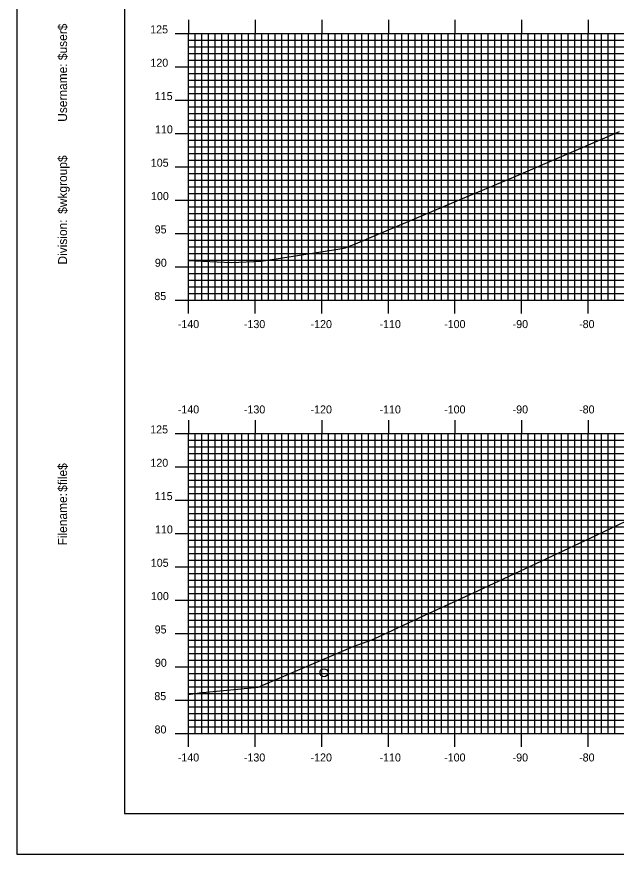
# Model space of a CAD drawing. Extents: x 1684405 to 1684749, y 461260 to 461480.
# Drawn here: x 1684405.4 to 1684495.4, y 461260 to 461385.6 of the extents above; entities that cross this region are included whole.
import ezdxf

# ---------------------------------------------------------------- set-up
doc = ezdxf.new("R2010")
doc.units = 0
for name, color, linetype in [('BORDER', 7, 'Continuous'), ('H_V ANNOTATION', 7, 'Continuous'), ('MAJOR', 7, 'Continuous'), ('MINOR', 7, 'Continuous'), ('PLOT BOUNDARY', 7, 'Continuous'), ('S_Drainage_Invert', 7, 'Continuous'), ('S_Roadway_Centerline', 7, 'Continuous')]:
    doc.layers.add(name, color=color, linetype=linetype)

msp = doc.modelspace()

# ---------------------------------------------------------------- linework, layer by layer
at = {"layer": 'BORDER'}
msp.add_lwpolyline([(1684421.6, 461266.07), (1684741.6, 461266.07), (1684741.6, 461476.07), (1684421.6, 461476.07)], close=True, dxfattribs=at)
at = {"layer": 'MAJOR'}
for p, q in [((1684431.2, 461385.08), (1684431.2, 461383.07)), ((1684441.2, 461385.08), (1684441.2, 461383.07)), ((1684451.2, 461385.08), (1684451.2, 461383.07)), ((1684461.2, 461385.08), (1684461.2, 461383.07)), ((1684471.2, 461385.08), (1684471.2, 461383.07)), ((1684481.2, 461385.08), (1684481.2, 461383.07)), ((1684491.2, 461385.08), (1684491.2, 461383.07)), ((1684429.2, 461383.07), (1684431.2, 461383.07)), ((1684431.2, 461383.07), (1684711.2, 461383.07)), ((1684431.2, 461343.07), (1684431.2, 461383.07)), ((1684431.2, 461343.07), (1684431.2, 461383.07)), ((1684431.2, 461383.07), (1684711.2, 461383.07)), ((1684441.2, 461343.07), (1684441.2, 461383.07)), ((1684451.2, 461343.07), (1684451.2, 461383.07)), ((1684461.2, 461343.07), (1684461.2, 461383.07)), ((1684471.2, 461343.07), (1684471.2, 461383.07)), ((1684481.2, 461343.07), (1684481.2, 461383.07)), ((1684491.2, 461343.07), (1684491.2, 461383.07)), ((1684429.2, 461378.07), (1684431.2, 461378.07)), ((1684431.2, 461378.07), (1684711.2, 461378.07)), ((1684429.2, 461373.07), (1684431.2, 461373.07)), ((1684431.2, 461373.07), (1684711.2, 461373.07)), ((1684429.2, 461368.07), (1684431.2, 461368.07)), ((1684431.2, 461368.07), (1684711.2, 461368.07)), ((1684429.2, 461363.07), (1684431.2, 461363.07)), ((1684431.2, 461363.07), (1684711.2, 461363.07)), ((1684429.2, 461358.07), (1684431.2, 461358.07)), ((1684431.2, 461358.07), (1684711.2, 461358.07)), ((1684429.2, 461353.07), (1684431.2, 461353.07)), ((1684431.2, 461353.07), (1684711.2, 461353.07)), ((1684429.2, 461348.07), (1684431.2, 461348.07)), ((1684431.2, 461348.07), (1684711.2, 461348.07)), ((1684429.2, 461343.07), (1684431.2, 461343.07)), ((1684431.2, 461343.07), (1684711.2, 461343.07)), ((1684431.2, 461343.07), (1684711.2, 461343.07)), ((1684431.2, 461341.07), (1684431.2, 461343.07)), ((1684441.2, 461341.07), (1684441.2, 461343.07)), ((1684451.2, 461341.07), (1684451.2, 461343.07)), ((1684461.2, 461341.07), (1684461.2, 461343.07)), ((1684471.2, 461341.07), (1684471.2, 461343.07)), ((1684481.2, 461341.07), (1684481.2, 461343.07)), ((1684491.2, 461341.07), (1684491.2, 461343.07)), ((1684431.2, 461325.08), (1684431.2, 461323.07)), ((1684441.2, 461325.08), (1684441.2, 461323.07)), ((1684451.2, 461325.08), (1684451.2, 461323.07)), ((1684461.2, 461325.08), (1684461.2, 461323.07)), ((1684471.2, 461325.08), (1684471.2, 461323.07)), ((1684481.2, 461325.08), (1684481.2, 461323.07)), ((1684491.2, 461325.08), (1684491.2, 461323.07)), ((1684429.2, 461323.07), (1684431.2, 461323.07)), ((1684431.2, 461323.07), (1684711.2, 461323.07)), ((1684431.2, 461278.07), (1684431.2, 461323.07)), ((1684431.2, 461278.07), (1684431.2, 461323.07)), ((1684431.2, 461323.07), (1684711.2, 461323.07)), ((1684441.2, 461278.07), (1684441.2, 461323.07)), ((1684451.2, 461278.07), (1684451.2, 461323.07)), ((1684461.2, 461278.07), (1684461.2, 461323.07)), ((1684471.2, 461278.07), (1684471.2, 461323.07)), ((1684481.2, 461278.07), (1684481.2, 461323.07)), ((1684491.2, 461278.07), (1684491.2, 461323.07)), ((1684429.2, 461318.07), (1684431.2, 461318.07)), ((1684431.2, 461318.07), (1684711.2, 461318.07)), ((1684429.2, 461313.07), (1684431.2, 461313.07)), ((1684431.2, 461313.07), (1684711.2, 461313.07)), ((1684429.2, 461308.07), (1684431.2, 461308.07)), ((1684431.2, 461308.07), (1684711.2, 461308.07)), ((1684429.2, 461303.07), (1684431.2, 461303.07)), ((1684431.2, 461303.07), (1684711.2, 461303.07)), ((1684429.2, 461298.07), (1684431.2, 461298.07)), ((1684431.2, 461298.07), (1684711.2, 461298.07)), ((1684429.2, 461293.07), (1684431.2, 461293.07)), ((1684431.2, 461293.07), (1684711.2, 461293.07)), ((1684429.2, 461288.07), (1684431.2, 461288.07)), ((1684431.2, 461288.07), (1684711.2, 461288.07)), ((1684429.2, 461283.07), (1684431.2, 461283.07)), ((1684431.2, 461283.07), (1684711.2, 461283.07)), ((1684429.2, 461278.07), (1684431.2, 461278.07)), ((1684431.2, 461278.07), (1684711.2, 461278.07)), ((1684431.2, 461278.07), (1684711.2, 461278.07)), ((1684431.2, 461276.07), (1684431.2, 461278.07)), ((1684441.2, 461276.07), (1684441.2, 461278.07)), ((1684451.2, 461276.07), (1684451.2, 461278.07)), ((1684461.2, 461276.07), (1684461.2, 461278.07)), ((1684471.2, 461276.07), (1684471.2, 461278.07)), ((1684481.2, 461276.07), (1684481.2, 461278.07)), ((1684491.2, 461276.07), (1684491.2, 461278.07))]:
    msp.add_line(p, q, dxfattribs=at)
at = {"layer": 'MINOR'}
for p, q in [((1684432.2, 461343.07), (1684432.2, 461383.07)), ((1684433.2, 461343.07), (1684433.2, 461383.07)), ((1684434.2, 461343.07), (1684434.2, 461383.07)), ((1684435.2, 461343.07), (1684435.2, 461383.07)), ((1684436.2, 461343.07), (1684436.2, 461383.07)), ((1684437.2, 461343.07), (1684437.2, 461383.07)), ((1684438.2, 461343.07), (1684438.2, 461383.07)), ((1684439.2, 461343.07), (1684439.2, 461383.07)), ((1684440.2, 461343.07), (1684440.2, 461383.07)), ((1684442.2, 461343.07), (1684442.2, 461383.07)), ((1684443.2, 461343.07), (1684443.2, 461383.07)), ((1684444.2, 461343.07), (1684444.2, 461383.07)), ((1684445.2, 461343.07), (1684445.2, 461383.07)), ((1684446.2, 461343.07), (1684446.2, 461383.07)), ((1684447.2, 461343.07), (1684447.2, 461383.07)), ((1684448.2, 461343.07), (1684448.2, 461383.07)), ((1684449.2, 461343.07), (1684449.2, 461383.07)), ((1684450.2, 461343.07), (1684450.2, 461383.07)), ((1684452.2, 461343.07), (1684452.2, 461383.07)), ((1684453.2, 461343.07), (1684453.2, 461383.07)), ((1684454.2, 461343.07), (1684454.2, 461383.07)), ((1684455.2, 461343.07), (1684455.2, 461383.07)), ((1684456.2, 461343.07), (1684456.2, 461383.07)), ((1684457.2, 461343.07), (1684457.2, 461383.07)), ((1684458.2, 461343.07), (1684458.2, 461383.07)), ((1684459.2, 461343.07), (1684459.2, 461383.07)), ((1684460.2, 461343.07), (1684460.2, 461383.07)), ((1684462.2, 461343.07), (1684462.2, 461383.07)), ((1684463.2, 461343.07), (1684463.2, 461383.07)), ((1684464.2, 461343.07), (1684464.2, 461383.07)), ((1684465.2, 461343.07), (1684465.2, 461383.07)), ((1684466.2, 461343.07), (1684466.2, 461383.07)), ((1684467.2, 461343.07), (1684467.2, 461383.07)), ((1684468.2, 461343.07), (1684468.2, 461383.07)), ((1684469.2, 461343.07), (1684469.2, 461383.07)), ((1684470.2, 461343.07), (1684470.2, 461383.07)), ((1684472.2, 461343.07), (1684472.2, 461383.07)), ((1684473.2, 461343.07), (1684473.2, 461383.07)), ((1684474.2, 461343.07), (1684474.2, 461383.07)), ((1684475.2, 461343.07), (1684475.2, 461383.07)), ((1684476.2, 461343.07), (1684476.2, 461383.07)), ((1684477.2, 461343.07), (1684477.2, 461383.07)), ((1684478.2, 461343.07), (1684478.2, 461383.07)), ((1684479.2, 461343.07), (1684479.2, 461383.07)), ((1684480.2, 461343.07), (1684480.2, 461383.07)), ((1684482.2, 461343.07), (1684482.2, 461383.07)), ((1684483.2, 461343.07), (1684483.2, 461383.07)), ((1684484.2, 461343.07), (1684484.2, 461383.07)), ((1684485.2, 461343.07), (1684485.2, 461383.07)), ((1684486.2, 461343.07), (1684486.2, 461383.07)), ((1684487.2, 461343.07), (1684487.2, 461383.07)), ((1684488.2, 461343.07), (1684488.2, 461383.07)), ((1684489.2, 461343.07), (1684489.2, 461383.07)), ((1684490.2, 461343.07), (1684490.2, 461383.07)), ((1684492.2, 461343.07), (1684492.2, 461383.07)), ((1684493.2, 461343.07), (1684493.2, 461383.07)), ((1684494.2, 461343.07), (1684494.2, 461383.07)), ((1684495.2, 461343.07), (1684495.2, 461383.07)), ((1684431.2, 461382.07), (1684711.2, 461382.07)), ((1684431.2, 461382.07), (1684433.21, 461382.07)), ((1684431.2, 461381.07), (1684711.2, 461381.07)), ((1684431.2, 461381.07), (1684433.21, 461381.07)), ((1684431.2, 461380.07), (1684711.2, 461380.07)), ((1684431.2, 461380.07), (1684433.21, 461380.07)), ((1684431.2, 461379.07), (1684711.2, 461379.07)), ((1684431.2, 461379.07), (1684433.21, 461379.07)), ((1684431.2, 461377.07), (1684711.2, 461377.07)), ((1684431.2, 461377.07), (1684433.21, 461377.07)), ((1684431.2, 461376.07), (1684711.2, 461376.07)), ((1684431.2, 461376.07), (1684433.21, 461376.07)), ((1684431.2, 461375.07), (1684711.2, 461375.07)), ((1684431.2, 461375.07), (1684433.21, 461375.07)), ((1684431.2, 461374.07), (1684711.2, 461374.07)), ((1684431.2, 461374.07), (1684433.21, 461374.07)), ((1684431.2, 461372.07), (1684711.2, 461372.07)), ((1684431.2, 461372.07), (1684433.21, 461372.07)), ((1684431.2, 461371.07), (1684711.2, 461371.07)), ((1684431.2, 461371.07), (1684433.21, 461371.07)), ((1684431.2, 461370.07), (1684711.2, 461370.07)), ((1684431.2, 461370.07), (1684433.21, 461370.07)), ((1684431.2, 461369.07), (1684711.2, 461369.07)), ((1684431.2, 461369.07), (1684433.21, 461369.07)), ((1684431.2, 461367.07), (1684711.2, 461367.07)), ((1684431.2, 461367.07), (1684433.21, 461367.07)), ((1684431.2, 461366.07), (1684711.2, 461366.07)), ((1684431.2, 461366.07), (1684433.21, 461366.07)), ((1684431.2, 461365.07), (1684711.2, 461365.07)), ((1684431.2, 461365.07), (1684433.21, 461365.07)), ((1684431.2, 461364.07), (1684711.2, 461364.07)), ((1684431.2, 461364.07), (1684433.21, 461364.07)), ((1684431.2, 461362.07), (1684711.2, 461362.07)), ((1684431.2, 461362.07), (1684433.21, 461362.07)), ((1684431.2, 461361.07), (1684711.2, 461361.07)), ((1684431.2, 461361.07), (1684433.21, 461361.07)), ((1684431.2, 461360.07), (1684711.2, 461360.07)), ((1684431.2, 461360.07), (1684433.21, 461360.07)), ((1684431.2, 461359.07), (1684711.2, 461359.07)), ((1684431.2, 461359.07), (1684433.21, 461359.07)), ((1684431.2, 461357.07), (1684711.2, 461357.07)), ((1684431.2, 461357.07), (1684433.21, 461357.07)), ((1684431.2, 461356.07), (1684711.2, 461356.07)), ((1684431.2, 461356.07), (1684433.21, 461356.07)), ((1684431.2, 461355.07), (1684711.2, 461355.07)), ((1684431.2, 461355.07), (1684433.21, 461355.07)), ((1684431.2, 461354.07), (1684711.2, 461354.07)), ((1684431.2, 461354.07), (1684433.21, 461354.07)), ((1684431.2, 461352.07), (1684711.2, 461352.07)), ((1684431.2, 461352.07), (1684433.21, 461352.07)), ((1684431.2, 461351.07), (1684711.2, 461351.07)), ((1684431.2, 461351.07), (1684433.21, 461351.07)), ((1684431.2, 461350.07), (1684711.2, 461350.07)), ((1684431.2, 461350.07), (1684433.21, 461350.07)), ((1684431.2, 461349.07), (1684711.2, 461349.07)), ((1684431.2, 461349.07), (1684433.21, 461349.07)), ((1684431.2, 461347.07), (1684711.2, 461347.07)), ((1684431.2, 461347.07), (1684433.21, 461347.07)), ((1684431.2, 461346.07), (1684711.2, 461346.07)), ((1684431.2, 461346.07), (1684433.21, 461346.07)), ((1684431.2, 461345.07), (1684711.2, 461345.07)), ((1684431.2, 461345.07), (1684433.21, 461345.07)), ((1684431.2, 461344.07), (1684711.2, 461344.07)), ((1684431.2, 461344.07), (1684433.21, 461344.07)), ((1684432.2, 461278.07), (1684432.2, 461323.07)), ((1684433.2, 461278.07), (1684433.2, 461323.07)), ((1684434.2, 461278.07), (1684434.2, 461323.07)), ((1684435.2, 461278.07), (1684435.2, 461323.07)), ((1684436.2, 461278.07), (1684436.2, 461323.07)), ((1684437.2, 461278.07), (1684437.2, 461323.07)), ((1684438.2, 461278.07), (1684438.2, 461323.07)), ((1684439.2, 461278.07), (1684439.2, 461323.07)), ((1684440.2, 461278.07), (1684440.2, 461323.07)), ((1684442.2, 461278.07), (1684442.2, 461323.07)), ((1684443.2, 461278.07), (1684443.2, 461323.07)), ((1684444.2, 461278.07), (1684444.2, 461323.07)), ((1684445.2, 461278.07), (1684445.2, 461323.07)), ((1684446.2, 461278.07), (1684446.2, 461323.07)), ((1684447.2, 461278.07), (1684447.2, 461323.07)), ((1684448.2, 461278.07), (1684448.2, 461323.07)), ((1684449.2, 461278.07), (1684449.2, 461323.07)), ((1684450.2, 461278.07), (1684450.2, 461323.07)), ((1684452.2, 461278.07), (1684452.2, 461323.07)), ((1684453.2, 461278.07), (1684453.2, 461323.07)), ((1684454.2, 461278.07), (1684454.2, 461323.07)), ((1684455.2, 461278.07), (1684455.2, 461323.07)), ((1684456.2, 461278.07), (1684456.2, 461323.07)), ((1684457.2, 461278.07), (1684457.2, 461323.07)), ((1684458.2, 461278.07), (1684458.2, 461323.07)), ((1684459.2, 461278.07), (1684459.2, 461323.07)), ((1684460.2, 461278.07), (1684460.2, 461323.07)), ((1684462.2, 461278.07), (1684462.2, 461323.07)), ((1684463.2, 461278.07), (1684463.2, 461323.07)), ((1684464.2, 461278.07), (1684464.2, 461323.07)), ((1684465.2, 461278.07), (1684465.2, 461323.07)), ((1684466.2, 461278.07), (1684466.2, 461323.07)), ((1684467.2, 461278.07), (1684467.2, 461323.07)), ((1684468.2, 461278.07), (1684468.2, 461323.07)), ((1684469.2, 461278.07), (1684469.2, 461323.07)), ((1684470.2, 461278.07), (1684470.2, 461323.07)), ((1684472.2, 461278.07), (1684472.2, 461323.07)), ((1684473.2, 461278.07), (1684473.2, 461323.07)), ((1684474.2, 461278.07), (1684474.2, 461323.07)), ((1684475.2, 461278.07), (1684475.2, 461323.07)), ((1684476.2, 461278.07), (1684476.2, 461323.07)), ((1684477.2, 461278.07), (1684477.2, 461323.07)), ((1684478.2, 461278.07), (1684478.2, 461323.07)), ((1684479.2, 461278.07), (1684479.2, 461323.07)), ((1684480.2, 461278.07), (1684480.2, 461323.07)), ((1684482.2, 461278.07), (1684482.2, 461323.07)), ((1684483.2, 461278.07), (1684483.2, 461323.07)), ((1684484.2, 461278.07), (1684484.2, 461323.07)), ((1684485.2, 461278.07), (1684485.2, 461323.07)), ((1684486.2, 461278.07), (1684486.2, 461323.07)), ((1684487.2, 461278.07), (1684487.2, 461323.07)), ((1684488.2, 461278.07), (1684488.2, 461323.07)), ((1684489.2, 461278.07), (1684489.2, 461323.07)), ((1684490.2, 461278.07), (1684490.2, 461323.07)), ((1684492.2, 461278.07), (1684492.2, 461323.07)), ((1684493.2, 461278.07), (1684493.2, 461323.07)), ((1684494.2, 461278.07), (1684494.2, 461323.07)), ((1684495.2, 461278.07), (1684495.2, 461323.07)), ((1684431.2, 461322.07), (1684711.2, 461322.07)), ((1684431.2, 461322.07), (1684433.21, 461322.07)), ((1684431.2, 461321.07), (1684711.2, 461321.07)), ((1684431.2, 461321.07), (1684433.21, 461321.07)), ((1684431.2, 461320.07), (1684711.2, 461320.07)), ((1684431.2, 461320.07), (1684433.21, 461320.07)), ((1684431.2, 461319.07), (1684711.2, 461319.07)), ((1684431.2, 461319.07), (1684433.21, 461319.07)), ((1684431.2, 461317.07), (1684711.2, 461317.07)), ((1684431.2, 461317.07), (1684433.21, 461317.07)), ((1684431.2, 461316.07), (1684711.2, 461316.07)), ((1684431.2, 461316.07), (1684433.21, 461316.07)), ((1684431.2, 461315.07), (1684711.2, 461315.07)), ((1684431.2, 461315.07), (1684433.21, 461315.07)), ((1684431.2, 461314.07), (1684711.2, 461314.07)), ((1684431.2, 461314.07), (1684433.21, 461314.07)), ((1684431.2, 461312.07), (1684711.2, 461312.07)), ((1684431.2, 461312.07), (1684433.21, 461312.07)), ((1684431.2, 461311.07), (1684711.2, 461311.07)), ((1684431.2, 461311.07), (1684433.21, 461311.07)), ((1684431.2, 461310.07), (1684711.2, 461310.07)), ((1684431.2, 461310.07), (1684433.21, 461310.07)), ((1684431.2, 461309.07), (1684711.2, 461309.07)), ((1684431.2, 461309.07), (1684433.21, 461309.07)), ((1684431.2, 461307.07), (1684711.2, 461307.07)), ((1684431.2, 461307.07), (1684433.21, 461307.07)), ((1684431.2, 461306.07), (1684711.2, 461306.07)), ((1684431.2, 461306.07), (1684433.21, 461306.07)), ((1684431.2, 461305.07), (1684711.2, 461305.07)), ((1684431.2, 461305.07), (1684433.21, 461305.07)), ((1684431.2, 461304.07), (1684711.2, 461304.07)), ((1684431.2, 461304.07), (1684433.21, 461304.07)), ((1684431.2, 461302.07), (1684711.2, 461302.07)), ((1684431.2, 461302.07), (1684433.21, 461302.07)), ((1684431.2, 461301.07), (1684711.2, 461301.07)), ((1684431.2, 461301.07), (1684433.21, 461301.07)), ((1684431.2, 461300.07), (1684711.2, 461300.07)), ((1684431.2, 461300.07), (1684433.21, 461300.07)), ((1684431.2, 461299.07), (1684711.2, 461299.07)), ((1684431.2, 461299.07), (1684433.21, 461299.07)), ((1684431.2, 461297.07), (1684711.2, 461297.07)), ((1684431.2, 461297.07), (1684433.21, 461297.07)), ((1684431.2, 461296.07), (1684711.2, 461296.07)), ((1684431.2, 461296.07), (1684433.21, 461296.07)), ((1684431.2, 461295.07), (1684711.2, 461295.07)), ((1684431.2, 461295.07), (1684433.21, 461295.07)), ((1684431.2, 461294.07), (1684711.2, 461294.07)), ((1684431.2, 461294.07), (1684433.21, 461294.07)), ((1684431.2, 461292.07), (1684711.2, 461292.07)), ((1684431.2, 461292.07), (1684433.21, 461292.07)), ((1684431.2, 461291.07), (1684711.2, 461291.07)), ((1684431.2, 461291.07), (1684433.21, 461291.07)), ((1684431.2, 461290.07), (1684711.2, 461290.07)), ((1684431.2, 461290.07), (1684433.21, 461290.07)), ((1684431.2, 461289.07), (1684711.2, 461289.07)), ((1684431.2, 461289.07), (1684433.21, 461289.07)), ((1684431.2, 461287.07), (1684711.2, 461287.07)), ((1684431.2, 461287.07), (1684433.21, 461287.07)), ((1684431.2, 461286.07), (1684711.2, 461286.07)), ((1684431.2, 461286.07), (1684433.21, 461286.07)), ((1684431.2, 461285.07), (1684711.2, 461285.07)), ((1684431.2, 461285.07), (1684433.21, 461285.07)), ((1684431.2, 461284.07), (1684711.2, 461284.07)), ((1684431.2, 461284.07), (1684433.21, 461284.07)), ((1684431.2, 461282.07), (1684711.2, 461282.07)), ((1684431.2, 461282.07), (1684433.21, 461282.07)), ((1684431.2, 461281.07), (1684711.2, 461281.07)), ((1684431.2, 461281.07), (1684433.21, 461281.07)), ((1684431.2, 461280.07), (1684711.2, 461280.07)), ((1684431.2, 461280.07), (1684433.21, 461280.07)), ((1684431.2, 461279.07), (1684711.2, 461279.07)), ((1684431.2, 461279.07), (1684433.21, 461279.07))]:
    msp.add_line(p, q, dxfattribs=at)
at = {"layer": 'PLOT BOUNDARY'}
msp.add_lwpolyline([(1684405.42, 461259.95), (1684745.42, 461259.95), (1684745.42, 461479.95), (1684405.42, 461479.95)], close=True, dxfattribs=at)
at = {"layer": 'S_Drainage_Invert'}
msp.add_circle((1684451.54, 461287.18), 0.6, dxfattribs=at)
at = {"layer": 'S_Roadway_Centerline'}
for points in [[(1684431.2, 461349.02), (1684437.65, 461348.72), (1684442.11, 461348.91), (1684453.29, 461350.68), (1684454.76, 461350.91), (1684456.64, 461351.68), (1684472.34, 461358.31), (1684479.27, 461361.19), (1684495.89, 461368.37)], [(1684431.2, 461283.91), (1684432.81, 461284.14), (1684441.67, 461285.03), (1684455.94, 461291.11), (1684458.7, 461292.09), (1684460.38, 461292.87), (1684467.32, 461296.12), (1684473.96, 461299.17), (1684478.59, 461301.32), (1684492.33, 461307.78), (1684500.28, 461311.57)]]:
    msp.add_lwpolyline(points, dxfattribs=at)

# ---------------------------------------------------------------- texts
at = {"layer": 'BORDER'}
for s, p in [('$user$', (1684412.97, 461379.06)), ('Username:', (1684412.97, 461369.81)), ('$wkgroup$', (1684412.97, 461356.01)), ('Division:', (1684412.97, 461348.4)), ('$file$', (1684412.97, 461314.32)), ('Filename:', (1684412.97, 461306.27))]:
    msp.add_text(s, height=1.339, rotation=90, dxfattribs=at).set_placement(p)
at = {"layer": 'H_V ANNOTATION'}
for s, p in [('125', (1684425.45, 461383.07)), ('120', (1684425.48, 461378.07)), ('115', (1684426.14, 461373.07)), ('110', (1684426.17, 461368.07)), ('105', (1684425.54, 461363.07)), ('100', (1684425.57, 461358.07)), ('95', (1684426.12, 461353.07)), ('90', (1684426.15, 461348.07)), ('85', (1684426.07, 461343.07)), ('-140', (1684429.59, 461338.87)), ('-130', (1684439.51, 461338.87)), ('-120', (1684449.52, 461338.87)), ('-110', (1684459.87, 461338.87)), ('-100', (1684469.57, 461338.87)), ('-90', (1684479.85, 461338.87)), ('-80', (1684489.83, 461338.87)), ('-140', (1684429.59, 461326.07)), ('-130', (1684439.51, 461326.07)), ('-120', (1684449.52, 461326.07)), ('-110', (1684459.87, 461326.07)), ('-100', (1684469.57, 461326.07)), ('-90', (1684479.85, 461326.07)), ('-80', (1684489.83, 461326.07)), ('125', (1684425.45, 461323.07)), ('120', (1684425.48, 461318.07)), ('115', (1684426.14, 461313.07)), ('110', (1684426.17, 461308.07)), ('105', (1684425.54, 461303.07)), ('100', (1684425.57, 461298.07)), ('95', (1684426.12, 461293.07)), ('90', (1684426.15, 461288.07)), ('85', (1684426.07, 461283.07)), ('80', (1684426.1, 461278.07)), ('-140', (1684429.59, 461273.87)), ('-130', (1684439.51, 461273.87)), ('-120', (1684449.52, 461273.87)), ('-110', (1684459.87, 461273.87)), ('-100', (1684469.57, 461273.87)), ('-90', (1684479.85, 461273.87)), ('-80', (1684489.83, 461273.87))]:
    msp.add_text(s, height=1.2, dxfattribs=at).set_placement(p)
at = {"layer": 'MAJOR'}
for p in [(1684431.19, 461343.07), (1684431.19, 461278.07)]:
    msp.add_text('-', height=0.012, dxfattribs=at).set_placement(p)

doc.saveas('drawing.dxf')
